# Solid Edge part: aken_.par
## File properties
Author: Blackblade
Template: Normal.par
Last saved by: Blackblade
Revision: 9
Application: Solid Edge
Density: 2595.000 kg/m^3
Accuracy: 0.990
Material: Glass, general industrial
Face Style: White (glass)
Fill Style: ANSI36(Marble)
Virtual Style: White (Glass)
Coef. of Thermal Exp: 0.0
Thermal Conductivity: 0.0
Specific Heat: 0.0
Modulus of Elasticity: 0.0
Poission's Ratio: 0.0
Yield Stress: 0.0
Ultimate Stress: 0.0
Elongation: 0.0
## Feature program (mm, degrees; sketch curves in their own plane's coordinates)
sketch for "unnamed Protrusion 1" plane through (12.7222, 0, -8.6126) normal (0, -1, 0) x-axis (1, 0, 0)
  line (-68.3447, 8.6126) -> (-68.3447, 9.6126)
  line (-68.3447, 9.6126) -> (-56.5549, 9.6126)
extrude "unnamed Protrusion 1" add finite 171.8154 symmetric
sketch for "valja_loige" plane through (0, 0, 0) normal (0, 0, 1) x-axis (1, 0, 0)
  arc centre (67.9255, -577.5355) radius 650 from (-116.8807, 45.6392) to (366.9641, -0.4082) cw
  arc centre (67.9255, 576.7191) radius 650 from (-116.8807, -46.4556) to (366.9641, -0.4082) ccw
  arc centre (-50.426, -0.4082) radius 80.8492 from (-131.2752, -0.4082) to (-116.8807, -46.4556) ccw
  arc centre (-50.426, -0.4082) radius 80.8492 from (-131.2752, -0.4082) to (-116.8807, 45.6392) cw
extrude "valja_loige" cut finite 70 along +normal
fillet "Round_2" radius 50
sketch used by "ExtrudedCutout_9" plane through (0, 0, 0) normal (0, 0, 1) x-axis (1, 0, 0)
extrude "ExtrudedCutout_9" cut finite 70 along +normal
sketch used by "rurgad_maha" plane through (29.3775, -0.4082, 0) normal (0, 0, -1) x-axis (0.998209, 0.05982, 0)
extrude "rurgad_maha" cut finite 70 along -normal
thinwall "Thinwall_4"  Thickness = 1 mm
sketch for "ExtrudedCutout_14" plane through (0, 0, 0) normal (0, -1, 0) x-axis (1, 0, 0)
  arc centre (18.5138, -251.8018) radius 315.3388 from (63.0788, 60.3721) to (101.2435, 52.4914) cw
  line (108.0549, 25.2688) -> (101.2435, 52.4914)
  line (108.0549, 25.2688) -> (63.0788, 25.2688)
  line (63.0788, 25.2688) -> (63.0788, 60.3721)
extrude "ExtrudedCutout_14" cut finite 165.0175 symmetric
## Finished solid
Body 1: solid body, 14 faces, 36 edges, 24 vertices.
  Faces by surface: plane 9, blend 4, cylinder 1
  Edges by curve: intersection 20, line 16
Bounding box of the edges (mm; curved faces can reach further): 44.976 x 139.748 x 35.103, from (63.0788, -70.2819, 25.2688) to (108.0549, 69.4656, 60.3721).
Cylindrical faces by radius (mm): R315.3388 x1
Planar faces by outward normal: -x 2, -z 1, oblique 6
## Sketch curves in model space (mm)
line (63.0788, 0, 25.2688) -> (63.0788, 0, 60.3721)
arc centre (18.5138, 0, -251.8018) radius 315.3388 from (63.0788, 0, 60.3721) through (82.283, 0, 57.0219) to (101.2435, 0, 52.4914)
line (108.0549, 0, 25.2688) -> (101.2435, 0, 52.4914)
line (108.0549, 0, 25.2688) -> (63.0788, 0, 25.2688)
line (114.3775, 70.8026, 0) -> (114.3775, -71.1868, 0)
arc centre (80.6302, -577.3194, 0) radius 649 from (-55.6225, 57.2168, 0) through (28.9293, 69.618, 0) to (114.3775, 70.8026, 0)
line (-55.6225, 57.2168, 0) -> (-55.6225, -57.6011, 0)
arc centre (80.6302, 576.9351, 0) radius 649 from (-55.6225, -57.6011, 0) through (28.9293, -70.0023, 0) to (114.3775, -71.1868, 0)
line (114.3775, 70.8026, 0) -> (114.3775, -71.6189, 0)
line (114.3775, -71.6189, 0) -> (-55.6225, -61.4313, 0)
line (-55.6225, -61.4313, 0) -> (-55.6225, 60.6149, 0)
line (-55.6225, 60.6149, 0) -> (114.3775, 70.8026, 0)
arc centre (67.9255, 576.7191, 0) radius 650 from (-116.8807, -46.4556, 0) through (129.5076, -70.3571, 0) to (366.9641, -0.4082, 0)
arc centre (-50.426, -0.4082, 0) radius 80.8492 from (-131.2752, -0.4082, 0) through (-127.5927, -24.5306, 0) to (-116.8807, -46.4556, 0)
arc centre (-50.426, -0.4082, 0) radius 80.8492 from (-131.2752, -0.4082, 0) through (-127.5927, 23.7142, 0) to (-116.8807, 45.6392, 0)
arc centre (67.9255, -577.5355, 0) radius 650 from (-116.8807, 45.6392, 0) through (129.5076, 69.5407, 0) to (366.9641, -0.4082, 0)
line (114.3775, 0, 0) -> (99.8137, 0, 58.2056)
arc centre (14.3775, 0, -245.3388) radius 315.3388 from (14.3775, 0, 70) through (57.5007, 0, 67.0375) to (99.8137, 0, 58.2056)
arc centre (-55.6225, 0, 70) radius 70 from (-43.8326, 0, 1) through (-2.1188, 0, 24.8629) to (14.3775, 0, 70)
line (-55.6225, 0, 1) -> (-43.8326, 0, 1)
line (-55.6225, 0, 0) -> (-55.6225, 0, 1)
line (14.3775, 0, 0) -> (-55.6225, 0, 0)
line (14.3775, 0, 0) -> (114.3775, 0, 0)
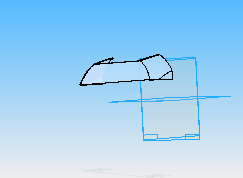
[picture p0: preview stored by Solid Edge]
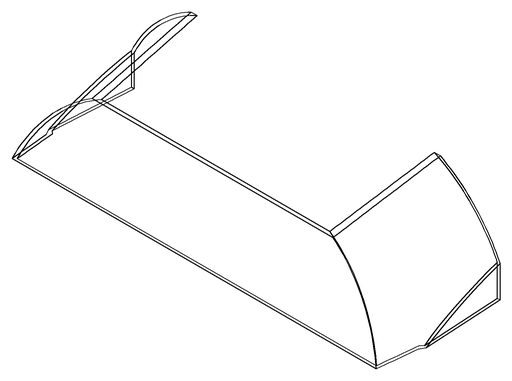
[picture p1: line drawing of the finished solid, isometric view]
